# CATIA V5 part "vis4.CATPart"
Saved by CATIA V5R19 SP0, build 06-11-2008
Part number: vis 4
Definition: NONE
Nomenclature: 1
Source: Unknown
Description: PART-1-DESC
Bounding box of the stored display mesh (mm): x -3.5 to 3.5, y -3.329 to 3.329, z -17 to 4
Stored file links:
  G:\EU_thinkMotion\CFAO_2010\MMS_groupe3\MMS_groupe3\A reprendre\ftixier\florent-tixier\florent-tixier\vis4.CATPart
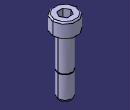
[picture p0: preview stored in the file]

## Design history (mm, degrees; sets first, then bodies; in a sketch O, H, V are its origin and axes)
Set1
  Sketch1 on xy-plane, origin (0, 0, 0), H (1, 0, 0), V (0, 1, 0)
    circle A1 centre (0, 0) radius 2
    reference projected arc E1 centre (0, 0) radius 3.1 from (-3.1, 0) to (3.1, 0) ccw from edge [face of Solid1 | face of Solid1]
    radius A1 = 2
    concentricity: A1 E1
Body1 "1" (main body)
  Solid1: solid without history
  Pad1: profile Sketch1, direction (0, 0, -1), length 17
  Sketch2 on zx-plane, origin (0, 0, 0), H (-1, 0, 0), V (0, 0, 1)
    circle A1 centre (2, -10) radius 0.1
    point P1 (2, -10)
    reference projected line E1 through (0, 0) direction (0, 1) from axis of face of Pad1
    distance P1 E1 = 2
    radius A1 = 0.1
    distance P1 H = 10
  Groove1: profile Sketch2, axis axis of face of Pad1, angle 360
  Sketch3 on yz-plane, origin (0, 0, 0), H (0, 1, 0), V (0, 0, 1)
    line L1 (-7.9523, -17) -> (7.6111, -17)
    line L2 (7.6111, -17) -> (7.6111, -26.6141)
    line L3 (7.6111, -26.6141) -> (-7.9523, -26.6141)
    line L4 (-7.9523, -26.6141) -> (-7.9523, -17)
    distance L1 H = 17
    horizontal: L1 H, L3 H
    vertical: L2 V, L4 V
  Pocket1: profile Sketch3, direction (-1, 0, 0), length 17, mirrored extent
  Chamfer1: length 0.3, angle 60, on edge [face of Pocket1 from Sketch3.L1 | face of Pad1]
